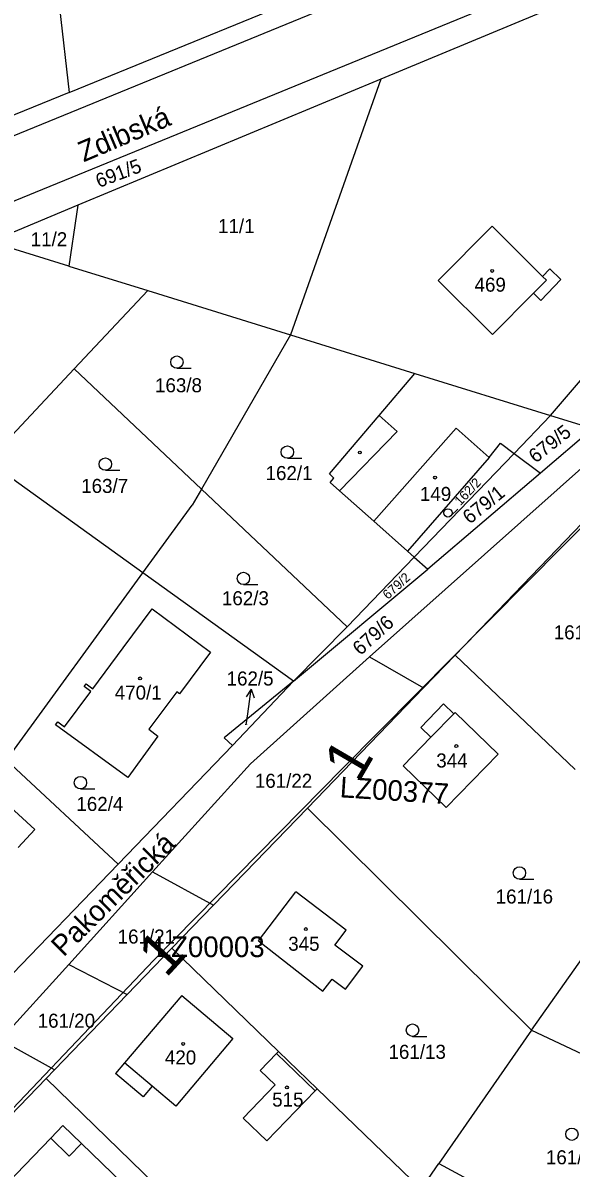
# Model space of a CAD drawing. Extents: x -738131 to -734179, y -1033447 to -1030078.
# Drawn here: x -736330.8 to -736264.3, y -1032442 to -1032303.4 of the extents above; entities that cross this region are included whole.
import ezdxf

# ---------------------------------------------------------------- set-up
doc = ezdxf.new("R2010")
doc.units = 0
for name, color, linetype in [('ftf_2050', 7, 'Continuous'), ('ftf_3010', 7, 'Continuous'), ('ftf_3010_ftf_3010_gtda_3015_gtda_3015_1', 7, 'Continuous'), ('ftf_nu', 7, 'Continuous'), ('Vrstva 1', 7, 'Continuous'), ('Vrstva 2', 7, 'Continuous'), ('Vrstva 3', 7, 'Continuous'), ('Vrstva 4', 7, 'Continuous'), ('Vrstva 5', 7, 'Continuous'), ('Vrstva 7', 7, 'Continuous')]:
    doc.layers.add(name, color=color, linetype=linetype)

msp = doc.modelspace()

# ---------------------------------------------------------------- linework, layer by layer
at = {"layer": 'ftf_2050'}
for points in [[(-736292.03, -1032393.62), (-736260.81, -1032362.16)], [(-736314.93, -1032416.87), (-736292.03, -1032393.62)], [(-736314.93, -1032416.87), (-736339.09, -1032442.19)]]:
    msp.add_lwpolyline(points, dxfattribs=at)
at = {"layer": 'Vrstva 1'}
for points in [[(-736220.77, -1032282.48), (-736287.41, -1032310.18)], [(-736327.52, -1032291.22), (-736325.19, -1032311.77)], [(-736266.82, -1032350.9), (-736216.01, -1032291.63)], [(-736346.81, -1032323.08), (-736277.07, -1032294.54)], [(-736274.85, -1032301.61), (-736344.52, -1032330.1)], [(-736325.19, -1032311.77), (-736301.01, -1032301.92)], [(-736287.41, -1032310.18), (-736324.11, -1032325.43)], [(-736287.41, -1032310.18), (-736298.36, -1032341.11)], [(-736325.19, -1032311.77), (-736356.43, -1032324.48)], [(-736324.11, -1032325.43), (-736334.74, -1032329.85)], [(-736324.11, -1032325.43), (-736324.28, -1032326.53)], [(-736324.28, -1032326.53), (-736325.2, -1032332.8)], [(-736280.47, -1032334.53), (-736273.91, -1032327.95)], [(-736273.91, -1032327.95), (-736267.79, -1032334.06)], [(-736325.2, -1032332.8), (-736334.74, -1032329.85)], [(-736325.2, -1032332.8), (-736315.64, -1032335.76)], [(-736266.91, -1032333.14), (-736267.79, -1032334.06)], [(-736265.57, -1032334.43), (-736266.91, -1032333.14)], [(-736273.88, -1032341.1), (-736280.47, -1032334.53)], [(-736267.99, -1032336.95), (-736265.57, -1032334.43)], [(-736315.64, -1032335.76), (-736324.58, -1032345.26)], [(-736315.64, -1032335.76), (-736298.36, -1032341.11)], [(-736268.88, -1032336.09), (-736273.88, -1032341.1)], [(-736268.88, -1032336.09), (-736267.99, -1032336.95)], [(-736298.36, -1032341.11), (-736309.15, -1032359.83)], [(-736298.36, -1032341.11), (-736283.26, -1032345.8)], [(-736324.58, -1032345.26), (-736335.08, -1032356.43)], [(-736324.58, -1032345.26), (-736309.15, -1032359.83)], [(-736287.61, -1032350.91), (-736283.26, -1032345.8)], [(-736283.26, -1032345.8), (-736266.82, -1032350.9)], [(-736293.64, -1032357.97), (-736287.61, -1032350.91)], [(-736288.77, -1032380.12), (-736256.49, -1032351.4)], [(-736266.82, -1032350.9), (-736271.25, -1032355.49)], [(-736266.82, -1032350.9), (-736261.72, -1032352.48)], [(-736261.72, -1032352.48), (-736268.06, -1032357.89)], [(-736274.26, -1032355.98), (-736272.9, -1032354.25)], [(-736272.9, -1032354.25), (-736271.25, -1032355.49)], [(-736274.26, -1032355.98), (-736284.18, -1032367.31)], [(-736271.25, -1032355.49), (-736283.36, -1032368.04)], [(-736271.25, -1032355.49), (-736268.06, -1032357.89)], [(-736316.23, -1032369.95), (-736335.08, -1032356.43)], [(-736293.08, -1032358.47), (-736293.64, -1032357.97)], [(-736293.54, -1032359.01), (-736293.08, -1032358.47)], [(-736268.06, -1032357.89), (-736281.69, -1032369.52)], [(-736309.15, -1032359.83), (-736310.26, -1032361.76)], [(-736309.15, -1032359.83), (-736291.5, -1032376.48)], [(-736292.41, -1032360), (-736293.54, -1032359.01)], [(-736288.26, -1032363.69), (-736292.41, -1032360)], [(-736278.41, -1032379.91), (-736259.94, -1032360.75)], [(-736316.23, -1032369.95), (-736310.26, -1032361.76)], [(-736284.18, -1032367.31), (-736288.26, -1032363.69)], [(-736283.36, -1032368.04), (-736291.5, -1032376.48)], [(-736284.18, -1032367.31), (-736283.36, -1032368.04)], [(-736283.36, -1032368.04), (-736281.69, -1032369.52)], [(-736332.76, -1032392.63), (-736316.23, -1032369.95)], [(-736297.97, -1032383.05), (-736316.23, -1032369.95)], [(-736297.97, -1032383.05), (-736281.69, -1032369.52)], [(-736318.63, -1032379.01), (-736315.11, -1032374.32)], [(-736315.11, -1032374.32), (-736308.03, -1032379.56)], [(-736291.5, -1032376.48), (-736297.97, -1032383.05)], [(-736322.32, -1032383.98), (-736318.63, -1032379.01)], [(-736308.03, -1032379.56), (-736311.79, -1032384.6)], [(-736288.77, -1032380.12), (-736303.2, -1032393.06)], [(-736288.77, -1032380.12), (-736282.24, -1032383.88)], [(-736278.41, -1032379.91), (-736282.24, -1032383.88)], [(-736263.86, -1032393.75), (-736278.41, -1032379.91)], [(-736323.36, -1032383.73), (-736323.11, -1032383.39)], [(-736322.57, -1032384.31), (-736323.36, -1032383.73)], [(-736323.11, -1032383.39), (-736322.32, -1032383.98)], [(-736297.97, -1032383.05), (-736306.39, -1032389.91)], [(-736297.97, -1032383.05), (-736305.37, -1032390.86)], [(-736325.74, -1032388.6), (-736322.57, -1032384.31)], [(-736312.11, -1032384.36), (-736315.51, -1032388.88)], [(-736311.79, -1032384.6), (-736312.11, -1032384.36)], [(-736282.24, -1032383.88), (-736296.29, -1032398.45)], [(-736279.79, -1032385.82), (-736282.56, -1032388.66)], [(-736278.55, -1032387.03), (-736279.79, -1032385.82)], [(-736326.83, -1032388.35), (-736326.57, -1032387.99)], [(-736326.57, -1032387.99), (-736325.74, -1032388.6)], [(-736278.4, -1032386.87), (-736278.55, -1032387.03)], [(-736273.18, -1032391.9), (-736278.4, -1032386.87)], [(-736318.06, -1032394.71), (-736326.83, -1032388.35)], [(-736315.51, -1032388.88), (-736314.43, -1032389.74)], [(-736282.56, -1032388.66), (-736281.32, -1032389.86)], [(-736329.32, -1032401.02), (-736340.76, -1032390.56)], [(-736314.43, -1032389.74), (-736318.06, -1032394.71)], [(-736306.39, -1032389.91), (-736305.37, -1032390.86)], [(-736281.32, -1032389.86), (-736284.7, -1032393.32)], [(-736319.23, -1032405.23), (-736305.37, -1032390.86)], [(-736279.48, -1032398.36), (-736273.18, -1032391.9)], [(-736332.76, -1032392.63), (-736319.23, -1032405.23)], [(-736315.06, -1032406.15), (-736303.2, -1032393.06)], [(-736279.48, -1032398.36), (-736284.7, -1032393.32)], [(-736307.68, -1032410.19), (-736296.29, -1032398.45)], [(-736296.29, -1032398.45), (-736269.14, -1032425.33)], [(-736329.32, -1032401.02), (-736331.35, -1032403.2)], [(-736319.23, -1032405.23), (-736333.1, -1032419.6)], [(-736325.22, -1032417.36), (-736315.06, -1032406.15)], [(-736315.06, -1032406.15), (-736307.68, -1032410.19)], [(-736302.23, -1032414.51), (-736297.72, -1032408.57)], [(-736291.61, -1032413.23), (-736297.72, -1032408.57)], [(-736312.74, -1032415.41), (-736307.68, -1032410.19)], [(-736292.97, -1032415.02), (-736291.61, -1032413.23)], [(-736312.74, -1032415.41), (-736318.15, -1032421.01)], [(-736312.74, -1032415.41), (-736299.79, -1032427.92)], [(-736302.23, -1032414.51), (-736294.44, -1032420.62)], [(-736289.59, -1032417.59), (-736292.97, -1032415.02)], [(-736269.14, -1032425.33), (-736261.63, -1032414.7)], [(-736333.5, -1032426.5), (-736325.22, -1032417.36)], [(-736325.22, -1032417.36), (-736318.15, -1032421.01)], [(-736291.7, -1032420.38), (-736289.59, -1032417.59)], [(-736294.44, -1032420.62), (-736293.28, -1032419.14)], [(-736293.28, -1032419.14), (-736291.7, -1032420.38)], [(-736318.15, -1032421.01), (-736326.95, -1032430.13)], [(-736311.54, -1032421.11), (-736318.45, -1032429.29)], [(-736311.54, -1032421.11), (-736305.34, -1032426.35)], [(-736269.14, -1032425.33), (-736280.36, -1032441.47)], [(-736269.14, -1032425.33), (-736230.99, -1032443.24)], [(-736326.95, -1032430.13), (-736333.5, -1032426.5)], [(-736305.34, -1032426.35), (-736312.23, -1032434.53)], [(-736302.02, -1032430.22), (-736300.04, -1032428.17)], [(-736300.04, -1032428.17), (-736299.79, -1032427.92)], [(-736299.79, -1032427.92), (-736295.12, -1032432.43)], [(-736318.45, -1032429.29), (-736319.55, -1032430.59)], [(-736326.95, -1032430.13), (-736327.97, -1032431.18)], [(-736316.2, -1032433.41), (-736319.55, -1032430.59)], [(-736300.22, -1032431.93), (-736302.02, -1032430.22)], [(-736327.97, -1032431.18), (-736345.34, -1032449.16)], [(-736327.97, -1032431.18), (-736295.63, -1032462.58)], [(-736315.11, -1032432.11), (-736316.2, -1032433.41)], [(-736312.23, -1032434.53), (-736315.11, -1032432.11)], [(-736304.08, -1032436), (-736300.22, -1032431.93)], [(-736295.36, -1032432.68), (-736301.2, -1032438.73)], [(-736295.12, -1032432.43), (-736295.36, -1032432.68)], [(-736295.12, -1032432.43), (-736282.53, -1032444.59)], [(-736301.2, -1032438.73), (-736304.08, -1032436)], [(-736325.93, -1032436.89), (-736327.4, -1032438.41)], [(-736325.93, -1032436.89), (-736323.7, -1032439.05)], [(-736327.4, -1032438.41), (-736333.74, -1032444.94)], [(-736323.7, -1032439.05), (-736318.73, -1032443.84)], [(-736282.53, -1032444.59), (-736280.36, -1032441.47)], [(-736280.36, -1032441.47), (-736240.39, -1032463.08)]]:
    msp.add_lwpolyline(points, dxfattribs=at)
at = {"layer": 'Vrstva 3'}
for p, q in [((-736312.12, -1032345.17), (-736310.37, -1032345.17)), ((-736298.73, -1032356.07), (-736296.98, -1032356.07)), ((-736320.79, -1032357.53), (-736319.04, -1032357.53)), ((-736278.91, -1032363.05), (-736278.06, -1032362.23)), ((-736304.06, -1032371.37), (-736302.31, -1032371.37)), ((-736323.81, -1032396.11), (-736322.06, -1032396.11)), ((-736270.6, -1032407.04), (-736268.85, -1032407.04)), ((-736283.56, -1032426.08), (-736281.81, -1032426.08))]:
    msp.add_line(p, q, dxfattribs=at)
for centre, radius in [((-736312.12, -1032344.42), 0.75), ((-736298.73, -1032355.32), 0.75), ((-736320.79, -1032356.78), 0.75), ((-736279.26, -1032362.69), 0.503), ((-736304.06, -1032370.62), 0.75), ((-736323.81, -1032395.36), 0.75), ((-736270.6, -1032406.29), 0.75), ((-736283.56, -1032425.33), 0.75), ((-736264.24, -1032437.93), 0.75)]:
    msp.add_circle(centre, radius, dxfattribs=at)
at = {"layer": 'Vrstva 4'}
for points in [[(-736267.32, -1032334.52), (-736268.88, -1032336.09)], [(-736267.79, -1032334.06), (-736267.32, -1032334.52)], [(-736285.43, -1032352.82), (-736287.61, -1032350.91)], [(-736292.41, -1032360), (-736285.43, -1032352.82)], [(-736288.26, -1032363.69), (-736278.27, -1032352.42)], [(-736278.27, -1032352.42), (-736274.26, -1032355.98)], [(-736281.32, -1032389.86), (-736278.55, -1032387.03)], [(-736300.04, -1032428.17), (-736295.36, -1032432.68)], [(-736315.11, -1032432.11), (-736318.45, -1032429.29)], [(-736325.16, -1032440.57), (-736327.4, -1032438.41)], [(-736323.7, -1032439.05), (-736325.16, -1032440.57)]]:
    msp.add_lwpolyline(points, dxfattribs=at)
at = {"layer": 'Vrstva 5'}
for centre in [(-736273.9, -1032333.39), (-736289.95, -1032355.37), (-736280.83, -1032358.41), (-736316.58, -1032382.73), (-736278.25, -1032390.92), (-736296.49, -1032413.08), (-736311.36, -1032426.99), (-736298.78, -1032432.26)]:
    msp.add_circle(centre, 0.175, dxfattribs=at)
at = {"layer": 'Vrstva 7'}
for p, q in [((-736303.1, -1032384.04), (-736303.73, -1032384.96)), ((-736303.52, -1032387.01), (-736303.1, -1032384.04)), ((-736303.1, -1032384.04), (-736302.74, -1032385.1))]:
    msp.add_line(p, q, dxfattribs=at)
msp.add_lwpolyline([(-736303.71, -1032388.36), (-736303.52, -1032387.01)], dxfattribs=at)

# ---------------------------------------------------------------- texts
at = {"layer": 'ftf_3010'}
for rotation, p in [(59.7552, (-736290.11, -1032395.49)), (47.45, (-736313.45, -1032419.1))]:
    msp.add_text('1', height=5.2, rotation=rotation, dxfattribs=at).set_placement(p)
at = {"layer": 'ftf_3010_ftf_3010_gtda_3015_gtda_3015_1'}
msp.add_text('LZ00377', height=2.5, rotation=356.3095, dxfattribs=at).set_placement((-736292.42, -1032397.12))
msp.add_text('LZ00003', height=2.5, dxfattribs=at).set_placement((-736314.68, -1032416.48))
at = {"layer": 'ftf_nu'}
for s, rotation, p in [('Zdibská', 23.0224, (-736323.42, -1032320.24)), ('Pakoměřická', 44.7774, (-736325.85, -1032416.54))]:
    msp.add_text(s, height=2.5, rotation=rotation, dxfattribs=at).set_placement(p)
at = {"layer": 'Vrstva 2'}
for s, height, rotation, p in [('691/5', 1.7, 20.7609, (-736321.57, -1032323.35)), ('679/5', 1.7, 38.3527, (-736268.64, -1032356.73)), ('162/2', 1.14, 46.8406, (-736277.76, -1032361.89)), ('679/1', 1.7, 39.0718, (-736276.62, -1032364.12)), ('679/2', 1.14, 42.3699, (-736286.54, -1032373.23)), ('679/6', 1.7, 42.5104, (-736289.87, -1032380.03))]:
    msp.add_text(s, height=height, rotation=rotation, dxfattribs=at).set_placement(p)
for s, height, p in [('11/1', 1.7, (-736307.13, -1032328.8)), ('11/2', 1.7, (-736329.84, -1032330.4)), ('469', 1.7, (-736276.04, -1032335.9)), ('163/8', 1.7, (-736314.77, -1032348.08)), ('162/1', 1.7, (-736301.37, -1032358.71)), ('163/7', 1.7, (-736323.72, -1032360.27)), ('149', 1.7, (-736282.66, -1032361.24)), ('162/3', 1.7, (-736306.66, -1032373.87)), ('161/33', 1.7, (-736266.44, -1032378)), ('470/1', 1.7, (-736319.65, -1032385.29)), ('162/5', 0.1, (-736303.88, -1032388.36)), ('344', 1.7, (-736280.68, -1032393.52)), ('161/22', 1.7, (-736302.67, -1032395.98)), ('162/4', 1.7, (-736324.3, -1032398.78)), ('161/16', 1.7, (-736273.48, -1032409.99)), ('161/21', 1.7, (-736319.3, -1032414.84)), ('345', 1.7, (-736298.62, -1032415.71)), ('161/20', 1.7, (-736328.99, -1032425.03)), ('420', 1.7, (-736313.57, -1032429.48)), ('161/13', 1.7, (-736286.47, -1032428.8)), ('515', 1.7, (-736300.57, -1032434.58)), ('161/14', 1.7, (-736267.39, -1032441.57))]:
    msp.add_text(s, height=height, dxfattribs=at).set_placement(p)
at = {"layer": 'Vrstva 7'}
msp.add_text('162/5', height=1.7, dxfattribs=at).set_placement((-736306.09, -1032383.59))

doc.saveas('drawing.dxf')
